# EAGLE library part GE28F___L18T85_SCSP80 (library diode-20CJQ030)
Intel StrataFlash® Wireless Memory (L18) 28F640L18, 28F128L18, 28F256L18 Package: SCSP-80 Description: The Intel StrataFlash® wireless memory (L18) device is the latest generation of Intel StrataFlash® memory devices featuring flexible, multiple-partition, dual operation. It provides high performance synchronous-burst read mode and asynchronous read mode using 1.8 V lowvoltage, multi-level cell (MLC) technology. High performance Read-While-Write/Erase -85 ns initial access -54 MHz with zero wait state, 14 ns clock-todata output synchronous-burst mode -25 ns asynchronous-page mode -4-, 8-, 16-, and continuous-word burst mode -Burst suspend -Programmable WAIT configuration -Buffered Enhanced Factory Programming (Buffered EFP): 5 µs/byte (Typ) -1.8 V low-power buffered and non-buffered programming at 7 µs/byte (Typ) Architecture -Asymmetrically-blocked architecture -Multiple 8-Mbit partitions: 64Mb and 128Mb devices -Multiple 16-Mbit partitions: 256Mb devices -Four 16-Kword parameter blocks: top or bottom configurations -64-Kword main blocks -Dual-operation: Read-While-Write (RWW) or Read-While-Erase (RWE) -Status register for partition and device status Power -1.7 V - 2.0 V VCC operation -I/O voltage: 1.35 V - 2.0 V, 1.7 V - 2.0 V -Standby current: 25 µA (Typ) -4-Word synchronous read current: 17 mA (Typ) at 54 MHz -Automatic Power Savings (APS) mode Please send any comments to: messi@users.sourceforge.net
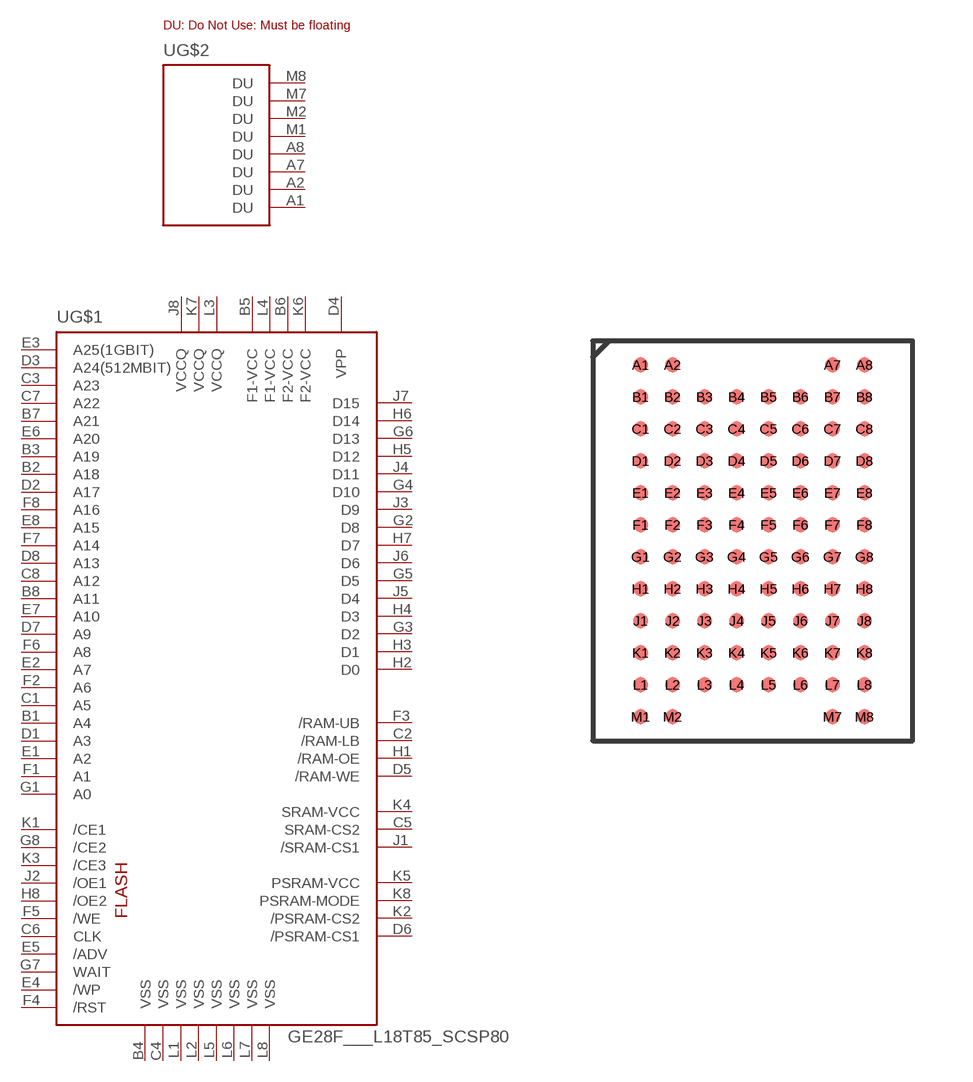
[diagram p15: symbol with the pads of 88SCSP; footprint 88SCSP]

Designator prefix U; gates G$2=GE28F_SCSP_DU G$1=GE28F_SCSP

## GE28F___L18T85_SCSP80  [88SCSP]
A1  G$2:DU
A2  G$2:DU
A7  G$2:DU
A8  G$2:DU
B1  G$1:A4  in
B2  G$1:A18  in
B3  G$1:A19  in
B4  G$1:VSS  pwr
B5  G$1:F1-VCC  pwr
B6  G$1:F2-VCC  nc
B7  G$1:A21  in
B8  G$1:A11  in
C1  G$1:A5  in
C2  G$1:/RAM-LB  nc
C3  G$1:A23  in
C4  G$1:VSS  pwr
C5  G$1:SRAM-CS2  in
C6  G$1:CLK  in
C7  G$1:A22  in
C8  G$1:A12  in
D1  G$1:A3  in
D2  G$1:A17  in
D3  G$1:A24(512MBIT)  in
D4  G$1:VPP  pwr
D5  G$1:/RAM-WE  nc
D6  G$1:/PSRAM-CS1  nc
D7  G$1:A9  in
D8  G$1:A13  in
E1  G$1:A2  in
E2  G$1:A7  in
E3  G$1:A25(1GBIT)  in
E4  G$1:/WP  in
E5  G$1:/ADV  in
E6  G$1:A20  in
E7  G$1:A10  in
E8  G$1:A15  in
F1  G$1:A1  in
F2  G$1:A6  in
F3  G$1:/RAM-UB  nc
F4  G$1:/RST  in
F5  G$1:/WE  in
F6  G$1:A8  in
F7  G$1:A14  in
F8  G$1:A16  in
G1  G$1:A0  in
G2  G$1:D8
G3  G$1:D2
G4  G$1:D10
G5  G$1:D5
G6  G$1:D13
G7  G$1:WAIT  out
G8  G$1:/CE2  in
H1  G$1:/RAM-OE  nc
H2  G$1:D0
H3  G$1:D1
H4  G$1:D3
H5  G$1:D12
H6  G$1:D14
H7  G$1:D7
H8  G$1:/OE2  in
J1  G$1:/SRAM-CS1  in
J2  G$1:/OE1  in
J3  G$1:D9
J4  G$1:D11
J5  G$1:D4
J6  G$1:D6
J7  G$1:D15
J8  G$1:VCCQ  pwr
K1  G$1:/CE1  in
K2  G$1:/PSRAM-CS2  nc
K3  G$1:/CE3  nc
K4  G$1:SRAM-VCC  nc
K5  G$1:PSRAM-VCC  nc
K6  G$1:F2-VCC  nc
K7  G$1:VCCQ  pwr
K8  G$1:PSRAM-MODE  nc
L1  G$1:VSS  pwr
L2  G$1:VSS  pwr
L3  G$1:VCCQ  pwr
L4  G$1:F1-VCC  pwr
L5  G$1:VSS  pwr
L6  G$1:VSS  pwr
L7  G$1:VSS  pwr
L8  G$1:VSS  pwr
M1  G$2:DU
M2  G$2:DU
M7  G$2:DU
M8  G$2:DU

## Footprint 88SCSP (pad centres in mm)
128-Mbit, 88-ball (80-active ball) Stacked Chip Scale Package (SCSP) pitch: 0.8 mm balldiameter: 0.375 Please send any comments to: messi@users.sourceforge.net
smd 0.375 x 0.375: A1 -2.8,4.4; A2 -2,4.4; A7 2,4.4; A8 2.8,4.4; B1 -2.8,3.6; B2 -2,3.6; B3 -1.2,3.6; B4 -0.4,3.6; B5 0.4,3.6; B6 1.2,3.6; B7 2,3.6; B8 2.8,3.6; C1 -2.8,2.8; C2 -2,2.8; C3 -1.2,2.8; C4 -0.4,2.8; C5 0.4,2.8; C6 1.2,2.8; C7 2,2.8; C8 2.8,2.8; D1 -2.8,2; D2 -2,2; D3 -1.2,2; D4 -0.4,2; D5 0.4,2; D6 1.2,2; D7 2,2; D8 2.8,2; E1 -2.8,1.2; E2 -2,1.2; E3 -1.2,1.2; E4 -0.4,1.2; E5 0.4,1.2; E6 1.2,1.2; E7 2,1.2; E8 2.8,1.2; F1 -2.8,0.4; F2 -2,0.4; F3 -1.2,0.4; F4 -0.4,0.4; F5 0.4,0.4; F6 1.2,0.4; F7 2,0.4; F8 2.8,0.4; G1 -2.8,-0.4; G2 -2,-0.4; G3 -1.2,-0.4; G4 -0.4,-0.4; G5 0.4,-0.4; G6 1.2,-0.4; G7 2,-0.4; G8 2.8,-0.4; H1 -2.8,-1.2; H2 -2,-1.2; H3 -1.2,-1.2; H4 -0.4,-1.2; H5 0.4,-1.2; H6 1.2,-1.2; H7 2,-1.2; H8 2.8,-1.2; J1 -2.8,-2; J2 -2,-2; J3 -1.2,-2; J4 -0.4,-2; J5 0.4,-2; J6 1.2,-2; J7 2,-2; J8 2.8,-2; K1 -2.8,-2.8; K2 -2,-2.8; K3 -1.2,-2.8; K4 -0.4,-2.8; K5 0.4,-2.8; K6 1.2,-2.8; K7 2,-2.8; K8 2.8,-2.8; L1 -2.8,-3.6; L2 -2,-3.6; L3 -1.2,-3.6; L4 -0.4,-3.6; L5 0.4,-3.6; L6 1.2,-3.6; L7 2,-3.6; L8 2.8,-3.6; M1 -2.8,-4.4; M2 -2,-4.4; M7 2,-4.4; M8 2.8,-4.4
